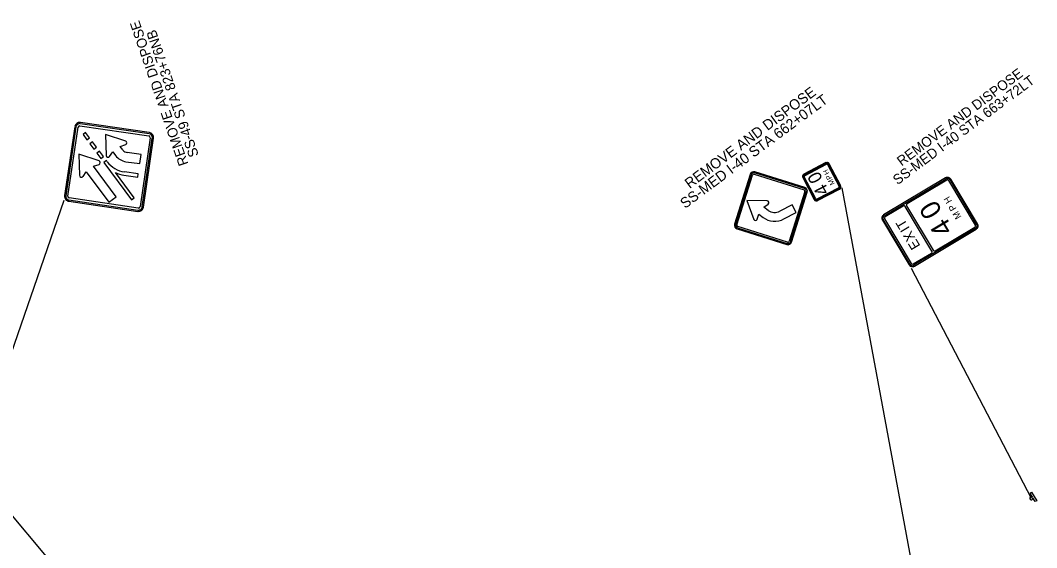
# Model space of a CAD drawing. Extents: x 641128 to 649424, y 422807 to 432853.
# Drawn here: x 644900 to 646125, y 426941 to 427576 of the extents above; entities that cross this region are included whole.
import ezdxf

# ---------------------------------------------------------------- set-up
doc = ezdxf.new("R2010")
doc.units = 0
for name, color, linetype in [('R_Dimension', 7, 'Continuous'), ('R_Dimension_2', 7, 'Continuous'), ('S_SIGN', 7, 'Continuous')]:
    doc.layers.add(name, color=color, linetype=linetype)

msp = doc.modelspace()

# ---------------------------------------------------------------- linework, layer by layer
at = {"layer": 'S_SIGN'}
for p, q in [((644965.8, 427448.2), (644953.6, 427365.1)), ((645055.7, 427441.1), (644972.6, 427453.3)), ((645027.2, 427430.8), (645003, 427438.9)), ((645003, 427438.9), (645003.8, 427413.4)), ((645048.6, 427351.2), (645060.8, 427434.3)), ((645007.9, 427412.2), (645011.9, 427417.8)), ((645011.9, 427417.8), (645015, 427413.5)), ((645020.7, 427424.3), (645027.2, 427426.6)), ((645023.9, 427420.1), (645020.7, 427424.3)), ((644995.1, 427406.9), (644970.9, 427415)), ((644970.9, 427415), (644971.7, 427389.5)), ((645004.1, 427407.3), (645000.8, 427404.9)), ((645000.8, 427404.9), (645034.3, 427360)), ((645005, 427406), (645004.1, 427407.3)), ((645027.5, 427406), (645044.1, 427403.6)), ((645045.7, 427414.5), (645029.1, 427416.9)), ((645044.1, 427403.6), (645045.7, 427414.5)), ((644975.8, 427388.3), (644979.8, 427393.9)), ((644979.8, 427393.9), (645007.1, 427357.2)), ((644988.6, 427400.5), (644995.1, 427402.7)), ((645015.9, 427363.8), (644988.6, 427400.5)), ((645037.5, 427362.4), (645014.8, 427392.9)), ((645042.3, 427391.2), (645025.7, 427393.7)), ((645845.3, 427374.8), (645785.2, 427393.7)), ((645870.7, 427404.8), (645844.1, 427390.9)), ((645888.6, 427376.9), (645874.7, 427403.5)), ((645025.1, 427389.7), (645041.7, 427387.3)), ((645041.7, 427387.3), (645042.3, 427391.2)), ((645779.6, 427390.7), (645760.7, 427330.6)), ((645842.8, 427386.8), (645856.7, 427360.2)), ((646014.9, 427386.5), (645940.3, 427341.7)), ((646053.5, 427330.9), (646021.1, 427384.9)), ((645829.4, 427309.1), (645848.3, 427369.2)), ((645860.7, 427359), (645887.3, 427372.9)), ((645890, 427374.3), (645974.6, 426917.5)), ((644952.8, 427359.2), (644863.5, 427100.8)), ((644958.7, 427358.3), (645041.8, 427346.1)), ((645007.1, 427357.2), (645015.9, 427363.8)), ((645034.3, 427360), (645037.5, 427362.4)), ((645799.9, 427358.7), (645775.6, 427359.3)), ((645775.6, 427359.3), (645783.8, 427336.4)), ((645795.9, 427351.1), (645801.1, 427354.9)), ((645801.2, 427347.3), (645795.9, 427351.1)), ((645830.3, 427354), (645815.4, 427346.3)), ((645820.2, 427337), (645835.1, 427344.7)), ((645835.1, 427344.7), (645830.3, 427354)), ((645787.8, 427336.5), (645789.8, 427342.6)), ((645789.8, 427342.6), (645795.1, 427338.8)), ((645938.8, 427335.5), (645971.2, 427281.5)), ((645763.7, 427325), (645823.8, 427306.1)), ((645977.4, 427280), (646052, 427324.7)), ((645973.5, 427277.7), (646118.2, 427000.2)), ((644944, 426915.5), (644741.6, 427157.1)), ((646116.8, 427006.4), (646118.5, 427007.4)), ((646119.6, 427001.6), (646116.8, 427006.4)), ((646118.5, 427007.4), (646124.7, 426997.1)), ((646119.6, 427001.6), (646119.6, 427001.6)), ((646123, 426996.1), (646120.1, 427000.8)), ((646120.1, 427000.8), (646120.1, 427000.8)), ((646124.7, 426997.1), (646123, 426996.1))]:
    msp.add_line(p, q, dxfattribs=at)
for points in [[(644967.3, 427448), (644955.1, 427364.9)], [(644957.6, 427364.5), (644969.8, 427447.6)], [(644967.3, 427448), (644967.3, 427448), (644967.3, 427448)], [(644972, 427449.3), (645055.2, 427437.2)], [(645055.5, 427439.6), (644972.4, 427451.8)], [(644979, 427441), (644975.8, 427438.6), (644980.5, 427432.2), (644983.7, 427434.6), (644979, 427441)], [(644987.3, 427429.8), (644984.1, 427427.4), (644988.9, 427421), (644992.1, 427423.4), (644987.3, 427429.8)], [(645056.8, 427434.9), (645044.7, 427351.8)], [(645047.1, 427351.4), (645059.3, 427434.5)], [(645055.5, 427439.6), (645055.5, 427439.6), (645055.5, 427439.6)], [(644995.7, 427418.6), (644992.5, 427416.2), (644997.3, 427409.7), (645000.5, 427412.1), (644995.7, 427418.6)], [(645871, 427404.1), (645844.4, 427390.2)], [(645845, 427389.1), (645871.6, 427403)], [(645871, 427404.1), (645871, 427404.1), (645871, 427404.1)], [(645872.9, 427402.6), (645886.8, 427376)], [(645887.9, 427376.6), (645874, 427403.2)], [(645780.8, 427390.3), (645761.9, 427330.2)], [(645763.6, 427329.7), (645782.4, 427389.8)], [(645780.8, 427390.3), (645780.8, 427390.3), (645780.8, 427390.3)], [(645784.3, 427390.8), (645844.4, 427372)], [(645845, 427373.6), (645784.8, 427392.5)], [(645843.5, 427387.2), (645857.4, 427360.6)], [(645843.5, 427387.2), (645843.5, 427387.2), (645843.5, 427387.2)], [(645858.5, 427361.2), (645844.6, 427387.8)], [(646014.9, 427386.5), (645940.3, 427341.7)], [(645941, 427340.6), (646015.6, 427385.4)], [(646016.3, 427383.8), (645968.5, 427355.1)], [(646014.9, 427386.5), (646014.9, 427386.5), (646014.9, 427386.5)], [(646050.8, 427329.6), (646018.7, 427383.2)], [(646020, 427384.3), (646052.4, 427330.3)], [(646053.5, 427330.9), (646021.1, 427384.9)], [(645845.4, 427370.1), (645826.6, 427310)], [(645828.2, 427309.4), (645847.1, 427369.5)], [(645845, 427373.6), (645845, 427373.6), (645845, 427373.6)], [(645886.4, 427374.6), (645859.8, 427360.7)], [(645860.4, 427359.6), (645887, 427373.5)], [(645887.9, 427376.6), (645887.9, 427376.6), (645887.9, 427376.6)], [(644958.9, 427359.8), (645042, 427347.6)], [(644958.9, 427359.8), (644958.9, 427359.8), (644958.9, 427359.8)], [(645042.4, 427350.1), (644959.3, 427362.3)], [(645860.4, 427359.6), (645860.4, 427359.6), (645860.4, 427359.6)], [(645047.1, 427351.4), (645047.1, 427351.4), (645047.1, 427351.4)], [(645964, 427352.4), (645942.1, 427339.3)], [(645998.5, 427298.2), (645966.4, 427351.8)], [(645967.9, 427352.7), (646000, 427299.1)], [(645938.8, 427335.5), (645971.2, 427281.5)], [(645938.8, 427335.5), (645938.8, 427335.5), (645938.8, 427335.5)], [(645972.3, 427282.2), (645939.9, 427336.2)], [(645941.5, 427336.9), (645973.6, 427283.3)], [(645764.1, 427326.1), (645824.2, 427307.3)], [(645764.1, 427326.1), (645764.1, 427326.1), (645764.1, 427326.1)], [(645824.7, 427309), (645764.6, 427327.8)], [(646051.3, 427325.8), (645976.7, 427281.1)], [(645977.4, 427280), (646052, 427324.7)], [(646002.4, 427298.5), (646050.2, 427327.2)], [(646050.8, 427329.6), (646050.8, 427329.6), (646050.8, 427329.6)], [(646053.5, 427330.9), (646053.5, 427330.9), (646053.5, 427330.9)], [(645828.2, 427309.4), (645828.2, 427309.4), (645828.2, 427309.4)], [(645976, 427282.7), (645997.9, 427295.8)], [(645998.5, 427298.2), (645998.5, 427298.2), (645998.5, 427298.2)], [(645977.4, 427280), (645977.4, 427280), (645977.4, 427280)]]:
    msp.add_lwpolyline(points, dxfattribs=at)
for centre, radius, start, end in [((644971.8, 427447.4), 6, 81.6644, 171.6641), ((644971.8, 427447.4), 4.5, 81.6644, 171.6641), ((644971.8, 427447.4), 2, 81.6644, 171.6641), ((645026.5, 427428.7), 2.25, 288.7801, 71.5119), ((645054.9, 427435.2), 2, 351.6645, 81.6642), ((645054.9, 427435.2), 4.5, 351.6645, 81.6642), ((645054.9, 427435.2), 6, 351.6645, 81.6642), ((645030.3, 427424.8), 8, 216.6642, 261.6643), ((644994.4, 427404.8), 2.25, 288.7801, 71.5119), ((645006, 427413.5), 2.25, 181.8169, 324.5487), ((645030.3, 427424.8), 31.5, 216.6642, 261.6643), ((645030.3, 427424.8), 19, 216.6642, 261.6643), ((645872, 427402.1), 3, 27.5985, 117.5987), ((645030.3, 427424.8), 35.5, 244.1255, 261.6643), ((645783.9, 427389.4), 4.5, 72.5986, 162.5983), ((645783.9, 427389.4), 3.25, 72.5986, 162.5983), ((645872, 427402.1), 2.25, 27.5985, 117.5987), ((645872, 427402.1), 1, 27.5985, 117.5987), ((644973.9, 427389.6), 2.25, 181.8169, 324.5487), ((645783.9, 427389.4), 1.5, 72.5986, 162.5983), ((645845.5, 427388.2), 3, 117.5985, 207.5987), ((645845.5, 427388.2), 2.25, 117.5985, 207.5987), ((645845.5, 427388.2), 1, 117.5985, 207.5987), ((646017.3, 427382.6), 4.5, 30.9596, 120.9598), ((646017.3, 427382.6), 4.5, 30.9596, 120.9598), ((646017.3, 427382.6), 3.25, 30.9596, 120.9598), ((646017.2, 427382.3), 1.75, 30.9596, 120.9598), ((645844, 427370.5), 1.5, 342.5984, 72.5986), ((645844, 427370.5), 3.25, 342.5984, 72.5986), ((645844, 427370.5), 4.5, 342.5984, 72.5986), ((645885.9, 427375.5), 1, 297.5983, 27.5985), ((645885.9, 427375.5), 2.25, 297.5983, 27.5985), ((645885.9, 427375.5), 3, 297.5983, 27.5985), ((644959.6, 427364.2), 6, 171.6641, 261.6643), ((644959.6, 427364.2), 4.5, 171.6641, 261.6643), ((644959.6, 427364.2), 2, 171.6641, 261.6643), ((645799.8, 427356.6), 2.13, 306.3262, 88.6053), ((645859.4, 427361.6), 3, 207.5987, 297.5983), ((645859.4, 427361.6), 2.25, 207.5987, 297.5983), ((645859.4, 427361.6), 1, 207.5987, 297.5983), ((645042.7, 427352.1), 6, 261.6643, 351.6645), ((645042.7, 427352.1), 4.5, 261.6643, 351.6645), ((645042.7, 427352.1), 2, 261.6643, 351.6645), ((645809.1, 427358.2), 13.5, 234.1541, 297.5983), ((645964.9, 427350.9), 1.75, 30.9596, 120.9598), ((645969.4, 427353.6), 1.75, 120.9595, 210.9597), ((645785.8, 427337.1), 2.13, 199.7027, 341.9819), ((645809.1, 427358.2), 24, 234.1541, 297.5983), ((645942.6, 427337.9), 4.5, 120.9595, 210.9597), ((645942.6, 427337.9), 4.5, 120.9595, 210.9597), ((645942.6, 427337.9), 3.25, 120.9595, 210.9597), ((645943, 427337.8), 1.75, 120.9595, 210.9597), ((645765, 427329.2), 4.5, 162.5985, 252.5982), ((645765, 427329.2), 3.25, 162.5985, 252.5982), ((645765, 427329.2), 1.5, 162.5985, 252.5982), ((646049.3, 427328.7), 1.75, 300.9594, 30.9596), ((646049.7, 427328.6), 3.25, 300.9594, 30.9596), ((646049.7, 427328.6), 4.5, 300.9594, 30.9596), ((646049.7, 427328.6), 4.5, 300.9594, 30.9596), ((645825.1, 427310.4), 4.5, 252.5982, 342.5984), ((645825.1, 427310.4), 3.25, 252.5982, 342.5984), ((645825.1, 427310.4), 1.5, 252.5982, 342.5984), ((645997, 427297.3), 1.75, 300.9594, 30.9596), ((646001.5, 427300), 1.75, 210.9597, 300.9594), ((645975.1, 427284.2), 1.75, 210.9597, 300.9594), ((645975.1, 427283.8), 4.5, 210.9597, 300.9594), ((645975.1, 427283.8), 4.5, 210.9597, 300.9594), ((645975.1, 427283.8), 3.25, 210.9597, 300.9594), ((646118.2, 427000.2), 2, 120.9595, 18.6396), ((646118.2, 427000.2), 2, 44.8216, 120.9595)]:
    msp.add_arc(centre, radius, start, end, dxfattribs=at)

# ---------------------------------------------------------------- texts
at = {"layer": 'R_Dimension'}
for s, height, p in [('REMOVE AND DISPOSE', 12, (645962, 427400.1)), ('SS-MED I-40 STA 663+72LT', 12, (645957.1, 427377.5)), ('REMOVE AND DISPOSE', 12.5, (645706.6, 427373)), ('SS-MED I-40 STA 662+07LT', 12.5, (645701.1, 427348.9))]:
    msp.add_text(s, height=height, rotation=36.6902, dxfattribs=at).set_placement(p)
at = {"layer": 'R_Dimension_2'}
for s, p in [('REMOVE AND DISPOSE', (645103, 427403.4)), ('SS-49 STA 823+76NB', (645115.4, 427413.9)), ('SS-RAMP I40EB-I49NB STA 138+59RT', (644926.1, 426751.6))]:
    msp.add_text(s, height=12, rotation=108.9552, dxfattribs=at).set_placement(p)
at = {"layer": 'S_SIGN'}
for s, height, rotation, p in [('0', 16, 117.5985, (645867.4, 427385.1)), ('H', 6, 117.5985, (645875.1, 427392)), ('P', 6, 117.5985, (645878.2, 427386.1)), ('M', 6, 117.5985, (645881.6, 427379.5)), ('4', 16, 117.5985, (645875.2, 427370.1)), ('0', 24, 120.9595, (646011.7, 427346.2)), ('H', 8, 120.9595, (646023, 427358.4)), ('P', 8, 120.9595, (646028.4, 427349.4)), ('M', 8, 120.9595, (646034.3, 427339.6)), ('T', 12, 120.9595, (645969.7, 427329.7)), ('4', 24, 120.9595, (646024.7, 427324.5)), ('I', 12, 120.9595, (645972.2, 427325.6)), ('X', 12, 120.9595, (645978.9, 427314.3)), ('E', 12, 120.9595, (645984.9, 427304.4))]:
    msp.add_text(s, height=height, rotation=rotation, dxfattribs=at).set_placement(p)

doc.saveas('drawing.dxf')
